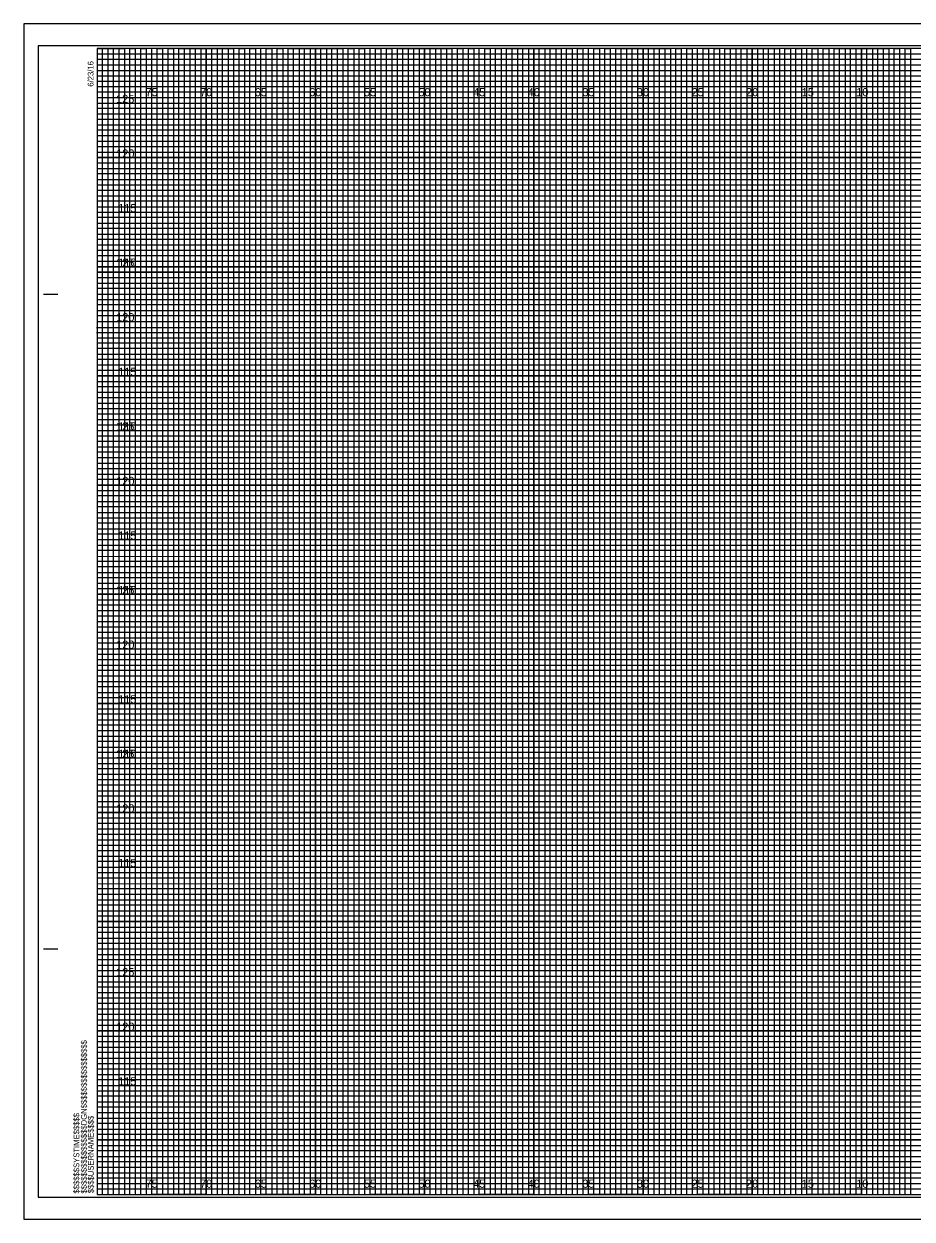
# Model space of a CAD drawing. Extents: x -7 to 182, y -2 to 1647.
# Drawn here: x -6.7 to 74.6, y 1427.8 to 1537.2 of the extents above; entities that cross this region are included whole.
import ezdxf

# ---------------------------------------------------------------- set-up
doc = ezdxf.new("R2010")
doc.units = 0
for name, color, linetype in [('Exist Cross Section Cell', 7, 'Continuous'), ('Exist XS Ground Line', 7, 'Continuous'), ('Prop CMT Pvmt Course 3', 7, 'Continuous'), ('Prop CMT Pvmt Wedge Surface 1', 7, 'Continuous'), ('Prop CMT Pvmt Wedge Surface 2', 7, 'Continuous'), ('Prop CMT Pvmt Wedge Surface 3', 7, 'Continuous'), ('Prop CMT Shld Paved Course 1', 7, 'Continuous'), ('Prop CMT Shld Paved Course 2', 7, 'Continuous'), ('Prop CMT Shld Paved Course 3', 7, 'Continuous'), ('Prop CMT Slope Grass', 7, 'Continuous'), ('Prop CMT Subgrade Earthwork', 7, 'Continuous')]:
    doc.layers.add(name, color=color, linetype=linetype)

msp = doc.modelspace()

# ---------------------------------------------------------------- linework, layer by layer
at = {"layer": 'Exist XS Ground Line'}
for p, q in [((5, 1535), (0, 1535)), ((5, 1430), (5, 1535)), ((15, 1535), (10, 1535)), ((10, 1535), (10, 1430)), ((15, 1430), (15, 1535)), ((25, 1535), (20, 1535)), ((20, 1535), (20, 1430)), ((25, 1430), (25, 1535)), ((35, 1535), (30, 1535)), ((30, 1535), (30, 1430)), ((35, 1430), (35, 1535)), ((45, 1535), (40, 1535)), ((40, 1535), (40, 1430)), ((45, 1430), (45, 1535)), ((55, 1535), (50, 1535)), ((50, 1535), (50, 1430)), ((55, 1430), (55, 1535)), ((65, 1535), (60, 1535)), ((60, 1535), (60, 1430)), ((65, 1430), (65, 1535)), ((75, 1535), (70, 1535)), ((70, 1535), (70, 1430)), ((10, 1430), (5, 1430)), ((20, 1430), (15, 1430)), ((30, 1430), (25, 1430)), ((40, 1430), (35, 1430)), ((50, 1430), (45, 1430)), ((60, 1430), (55, 1430)), ((70, 1430), (65, 1430))]:
    msp.add_line(p, q, dxfattribs=at)
for points in [[(0, 1530), (160, 1530), (160, 1525), (0, 1525)], [(0, 1520), (160, 1520), (160, 1515), (0, 1515)], [(0, 1510), (160, 1510), (160, 1505), (0, 1505)], [(0, 1500), (160, 1500), (160, 1495), (0, 1495)], [(0, 1490), (160, 1490), (160, 1485), (0, 1485)], [(0, 1480), (160, 1480), (160, 1475), (0, 1475)], [(0, 1470), (160, 1470), (160, 1465), (0, 1465)], [(0, 1460), (160, 1460), (160, 1455), (0, 1455)], [(0, 1450), (160, 1450), (160, 1445), (0, 1445)], [(0, 1440), (160, 1440), (160, 1435), (0, 1435)]]:
    msp.add_lwpolyline(points, dxfattribs=at)
at = {"layer": 'Prop CMT Pvmt Course 3'}
msp.add_lwpolyline([(-6.7, 1427.75), (161.65, 1427.75), (161.65, 1537.25), (-6.7, 1537.25)], close=True, dxfattribs=at)
at = {"layer": 'Prop CMT Pvmt Wedge Surface 1'}
for p, q in [((0, 1534.5), (130, 1534.5)), ((130, 1533.99), (0, 1533.99)), ((0, 1533.99), (0, 1533.5)), ((0, 1533.5), (130, 1533.5)), ((130, 1532.94), (0, 1532.94)), ((0, 1532.94), (0, 1532)), ((0, 1532), (160, 1532))]:
    msp.add_line(p, q, dxfattribs=at)
for points in [[(0, 1531.5), (135, 1531.5), (160, 1531.5), (160, 1531), (0, 1531)], [(0, 1530.5), (160, 1530.5), (160, 1529.5), (0, 1529.5)], [(0, 1529), (160, 1529), (160, 1528.5), (0, 1528.49)], [(0, 1528), (160, 1528), (160, 1527), (0, 1527)], [(0, 1526.5), (160, 1526.5), (160, 1526), (0, 1526)], [(0, 1525.5), (160, 1525.5), (160, 1524.5), (0, 1524.5)], [(0, 1524), (160, 1524), (160, 1523.5), (0, 1523.5)], [(0, 1523), (160, 1523), (160, 1522), (0, 1522)], [(0, 1521.5), (160, 1521.5), (160, 1521), (0, 1521)], [(0, 1520.5), (160, 1520.5), (160, 1519.5), (0, 1519.5)], [(0, 1519), (160, 1519), (160, 1518.5), (0, 1518.5)], [(0, 1518), (160, 1518), (160, 1516.98), (160, 1516.5), (160, 1516), (0, 1516)], [(0, 1517), (160, 1517), (160, 1516.5), (0, 1516.5)], [(0, 1515.5), (160, 1515.5), (160, 1514.5), (0, 1514.52)], [(0, 1514.52), (160, 1514.5), (160, 1514), (0, 1514)], [(0, 1513.5), (160, 1513.5), (160, 1513), (0, 1513)], [(0, 1512), (160, 1512), (160, 1511.5), (0, 1511.5)], [(0, 1511), (160, 1511), (160, 1510.5), (0, 1510.5)], [(-0.04, 1509.44), (160, 1509.44), (160, 1508.94), (-0.04, 1508.94)], [(0, 1508.5), (160, 1508.5), (160, 1508), (0, 1508)], [(0, 1507), (160, 1507), (160, 1506.5), (0, 1506.5)], [(0, 1506), (160, 1506), (160, 1505.5), (0, 1505.5)], [(0, 1504.5), (160, 1504.5), (160, 1504), (0, 1504)], [(0, 1503.5), (160, 1503.5), (160, 1503), (0, 1503)], [(0, 1502), (160, 1502), (160, 1501.5), (0, 1501.5)], [(0, 1501), (160, 1501), (160, 1500.5), (0, 1500.5)], [(0, 1499.5), (160, 1499.5), (160, 1498.99), (0, 1499)], [(0, 1498.5), (160, 1498.5), (160, 1498), (0, 1498)], [(0, 1497), (160, 1497), (160, 1496.5), (0, 1496.5)], [(0, 1496), (160, 1496), (160, 1495.5), (0, 1495.5)], [(0, 1494.5), (160, 1494.5), (160, 1494), (0, 1494)], [(0, 1493.5), (160, 1493.5), (160, 1493), (0, 1493)], [(0, 1492), (160, 1492), (160, 1491.5), (0, 1491.5)], [(0, 1491), (160, 1491), (160, 1490.5), (0, 1490.5)], [(0, 1489.5), (160, 1489.5), (160, 1489), (0, 1489)], [(0, 1488.5), (160.03, 1488.45), (160, 1488), (0, 1488)], [(0, 1487), (160, 1487), (160, 1486.5), (0, 1486.5)], [(0, 1486), (160, 1486), (160, 1485.5), (0, 1485.5)], [(0, 1484.5), (160, 1484.5), (160, 1484), (0, 1484)], [(0, 1483.5), (160, 1483.5), (160, 1483), (0, 1483)], [(0, 1482), (160, 1482), (160, 1481.5), (0, 1481.5)], [(0, 1481), (160, 1481), (160, 1480.5), (0, 1480.5)], [(0, 1479.5), (160, 1479.5), (160, 1479), (0, 1479)], [(0, 1478.5), (160, 1478.5), (160, 1478), (0, 1478)], [(0, 1477), (160, 1477), (160, 1476.5), (0, 1476.5)], [(0, 1476), (160, 1476), (160, 1475.5), (0, 1475.5)], [(0, 1474.5), (160, 1474.5), (160, 1474), (0, 1474)], [(0, 1473.5), (160, 1473.5), (160, 1473), (0, 1473)], [(0, 1472), (160, 1472), (160, 1471.5), (0, 1471.5)], [(0, 1471), (160, 1471), (160, 1470.5), (0, 1470.5)], [(0, 1469.5), (160, 1469.5), (160, 1468.99), (0, 1469)], [(0, 1468.5), (160, 1468.5), (160, 1468), (0, 1468)], [(0, 1467), (160, 1467), (160, 1466.5), (0, 1466.5)], [(0, 1466), (160, 1466), (160, 1465.5), (0, 1465.5)], [(0, 1464.5), (160, 1464.5), (160, 1464), (0, 1464)], [(0, 1463.5), (160, 1463.5), (160, 1463), (0, 1463)], [(0, 1462), (160, 1462), (160, 1461.5), (0, 1461.5)], [(0, 1461), (160, 1461), (160, 1460.5), (0, 1460.5)], [(0, 1459.5), (160, 1459.5), (160, 1459), (0, 1459)], [(0, 1458.5), (160.03, 1458.45), (160, 1458), (0, 1458)], [(0, 1457), (160, 1457), (160, 1456.5), (0, 1456.5)], [(0, 1456), (160, 1456), (160, 1455.5), (0, 1455.5)], [(0, 1454.5), (160, 1454.5), (160, 1454), (0, 1454)], [(0, 1453.5), (160, 1453.5), (160, 1453), (0, 1453)], [(0, 1452), (160, 1452), (160, 1451.5), (0, 1451.5)], [(0, 1451), (160, 1451), (160, 1450.5), (0, 1450.5)], [(0, 1449.5), (160, 1449.5), (160, 1449), (0, 1449)], [(0, 1448.5), (160, 1448.5), (160, 1448), (0, 1448)], [(0, 1447), (160, 1447), (160, 1446.5), (0, 1446.5)], [(0, 1446), (160, 1446), (160, 1445.5), (0, 1445.5)], [(0, 1444.5), (160, 1444.5), (160, 1444), (0, 1444)], [(0, 1443.5), (160, 1443.5), (160, 1443), (0, 1443)], [(0, 1442), (160, 1442), (160, 1441.5), (0, 1441.5)], [(0, 1441), (160, 1441), (160, 1440.5), (0, 1440.5)], [(0, 1439.5), (160, 1439.5), (160, 1439), (0, 1439)], [(0, 1438.5), (160, 1438.5), (160, 1438), (0, 1438)], [(0, 1437), (160, 1437), (160, 1436.5), (0, 1436.5)], [(0, 1436), (160, 1436), (160, 1435.5), (0, 1435.5)], [(0, 1434.5), (160, 1434.5), (160, 1434), (0, 1434)], [(0, 1433.5), (160, 1433.5), (160, 1433), (0, 1433)], [(0, 1432), (160, 1432), (160, 1431.5), (0, 1431.5)], [(0, 1431), (160, 1431), (160, 1430.5), (0, 1430.5)]]:
    msp.add_lwpolyline(points, dxfattribs=at)
at = {"layer": 'Prop CMT Pvmt Wedge Surface 2'}
for p, q in [((-4.9, 1512.5), (-3.65, 1512.5)), ((-4.85, 1512.5), (-3.6, 1512.5)), ((-4.9, 1452.5), (-3.65, 1452.5)), ((-4.85, 1452.5), (-3.6, 1452.5)), ((0, 1430), (0, 1430)), ((0, 1430), (0, 1430)), ((0, 1430), (0, 1430)), ((0, 1430), (0, 1430)), ((0, 1430), (0, 1430)), ((0, 1430), (0, 1430)), ((0, 1430), (0, 1430))]:
    msp.add_line(p, q, dxfattribs=at)
msp.add_lwpolyline([(160, 1535), (0, 1535), (0, 1430), (160, 1430)], close=True, dxfattribs=at)
at = {"layer": 'Prop CMT Pvmt Wedge Surface 3'}
for points in [[(0, 1430), (0.5, 1430), (0.5, 1535), (1, 1535), (1, 1430)], [(1, 1430), (1.5, 1430), (1.5, 1535), (2, 1535), (2, 1430)], [(2.5, 1430), (3, 1430), (3, 1535), (3.5, 1535), (3.5, 1430)], [(3.5, 1430), (4, 1430), (4, 1535), (4.5, 1535), (4.5, 1430)], [(5, 1430), (5.5, 1430), (5.5, 1535), (6, 1535), (6, 1430)], [(6, 1430), (6.5, 1430), (6.5, 1535), (7, 1535), (7, 1430)], [(7.5, 1430), (8, 1430), (8, 1535), (8.5, 1535), (8.5, 1430)], [(8.5, 1430), (9, 1430), (9, 1535), (9.5, 1535), (9.5, 1430)], [(10, 1430), (10.5, 1430), (10.5, 1535), (11, 1535), (11, 1430)], [(11, 1430), (11.5, 1430), (11.5, 1535), (12, 1535), (12, 1430)], [(12.5, 1430), (13, 1430), (13, 1535), (13.5, 1535), (13.5, 1430)], [(13.5, 1430), (14, 1430), (14, 1535), (14.5, 1535), (14.5, 1430)], [(15, 1430), (15.5, 1430), (15.5, 1535), (16, 1535), (16, 1430)], [(16, 1430), (16.5, 1430), (16.5, 1535), (17, 1535), (17, 1430)], [(17.5, 1430), (18, 1430), (18, 1535), (18.5, 1535), (18.5, 1430)], [(18.5, 1430), (19, 1430), (19, 1535), (19.5, 1535), (19.5, 1430)], [(20, 1430), (20.5, 1430), (20.5, 1535), (21, 1535), (21, 1430)], [(21, 1430), (21.5, 1430), (21.5, 1535), (22, 1535), (22, 1430)], [(22.5, 1430), (23, 1430), (23, 1535), (23.5, 1535), (23.5, 1430)], [(23.5, 1430), (24, 1430), (24, 1535), (24.5, 1535), (24.5, 1430)], [(25, 1430), (25.5, 1430), (25.5, 1535), (26, 1535), (26, 1430)], [(26, 1430), (26.5, 1430), (26.5, 1535), (27, 1535), (27, 1430)], [(27.5, 1430), (28, 1430), (28, 1535), (28.5, 1535), (28.5, 1430)], [(28.5, 1430), (29, 1430), (29, 1535), (29.5, 1535), (29.5, 1430)], [(30, 1430), (30.5, 1430), (30.5, 1535), (31, 1535), (31, 1430)], [(31, 1430), (31.5, 1430), (31.5, 1535), (32, 1535), (32, 1430)], [(32.5, 1430), (33, 1430), (33, 1535), (33.5, 1535), (33.5, 1430)], [(33.5, 1430), (34, 1430), (34, 1535), (34.5, 1535), (34.5, 1430)], [(35, 1430), (35.5, 1430), (35.5, 1535), (36, 1535), (36, 1430)], [(36, 1430), (36.5, 1430), (36.5, 1535), (37, 1535), (37, 1430)], [(37.5, 1430), (38, 1430), (38, 1535), (38.5, 1535), (38.5, 1430)], [(38.5, 1430), (39, 1430), (39, 1535), (39.5, 1535), (39.5, 1430)], [(40, 1430), (40.5, 1430), (40.5, 1535), (41, 1535), (41, 1430)], [(41, 1430), (41.5, 1430), (41.5, 1535), (42, 1535), (42, 1430)], [(42.5, 1430), (43, 1430), (43, 1535), (43.5, 1535), (43.5, 1430)], [(43.5, 1430), (44, 1430), (44, 1535), (44.5, 1535), (44.5, 1430)], [(45, 1430), (45.5, 1430), (45.5, 1535), (46, 1535), (46, 1430)], [(46, 1430), (46.5, 1430), (46.5, 1535), (47, 1535), (47, 1430)], [(47.5, 1430), (48, 1430), (48, 1535), (48.5, 1535), (48.5, 1430)], [(48.5, 1430), (49, 1430), (49, 1535), (49.5, 1535), (49.5, 1430)], [(50, 1430), (50.5, 1430), (50.5, 1535), (51, 1535), (51, 1430)], [(51, 1430), (51.5, 1430), (51.5, 1535), (52, 1535), (52, 1430)], [(52.5, 1430), (53, 1430), (53, 1535), (53.5, 1535), (53.5, 1430)], [(53.5, 1430), (54, 1430), (54, 1535), (54.5, 1535), (54.5, 1430)], [(55, 1430), (55.5, 1430), (55.5, 1535), (56, 1535), (56, 1430)], [(56, 1430), (56.5, 1430), (56.5, 1535), (57, 1535), (57, 1430)], [(57.5, 1430), (58, 1430), (58, 1535), (58.5, 1535), (58.5, 1430)], [(58.5, 1430), (59, 1430), (59, 1535), (59.5, 1535), (59.5, 1430)], [(60, 1430), (60.5, 1430), (60.5, 1535), (61, 1535), (61, 1430)], [(61, 1430), (61.5, 1430), (61.5, 1535), (62, 1535), (62, 1430)], [(62.5, 1430), (63, 1430), (63, 1535), (63.5, 1535), (63.5, 1430)], [(63.5, 1430), (64, 1430), (64, 1535), (64.5, 1535), (64.5, 1430)], [(65, 1430), (65.5, 1430), (65.5, 1535), (66, 1535), (66, 1430)], [(66, 1430), (66.5, 1430), (66.5, 1535), (67, 1535), (67, 1430)], [(67.5, 1430), (68, 1430), (68, 1535), (68.5, 1535), (68.5, 1430)], [(68.5, 1430), (69, 1430), (69, 1535), (69.5, 1535), (69.5, 1430)], [(70, 1430), (70.5, 1430), (70.5, 1535), (71, 1535), (71, 1430)], [(71, 1430), (71.5, 1430), (71.5, 1535), (72, 1535), (72, 1430)], [(72.5, 1430), (73, 1430), (73, 1535), (73.5, 1535), (73.5, 1430)], [(73.5, 1430), (74, 1430), (74, 1535), (74.5, 1535), (74.5, 1430)]]:
    msp.add_lwpolyline(points, dxfattribs=at)
at = {"layer": 'Prop CMT Shld Paved Course 1'}
for p, q in [((5, 1430), (5, 1535)), ((10, 1430), (10, 1535)), ((15, 1430), (15, 1535)), ((20, 1430), (20, 1535)), ((25, 1430), (25, 1535)), ((30, 1430), (30, 1535)), ((35, 1430), (35, 1535)), ((40, 1430), (40, 1535)), ((45, 1430), (45, 1535)), ((50, 1430), (50, 1535)), ((55, 1430), (55, 1535)), ((60, 1430), (60, 1535)), ((65, 1430), (65, 1535)), ((70, 1430), (70, 1535)), ((0, 1530), (160, 1530)), ((0, 1525), (160, 1525)), ((0, 1520), (160, 1520)), ((0, 1515), (160, 1515)), ((0, 1510), (160, 1510)), ((0, 1505), (160, 1505)), ((0, 1500), (160, 1500)), ((0, 1495), (160, 1495)), ((0, 1490), (160, 1490)), ((0, 1485), (160, 1485)), ((0, 1480), (160, 1480)), ((0, 1475), (160, 1475)), ((0, 1470), (160, 1470)), ((0, 1465), (160, 1465)), ((0, 1460), (160, 1460)), ((0, 1455), (160, 1455)), ((0, 1450), (160, 1450)), ((0, 1445), (160, 1445)), ((0, 1440), (160, 1440)), ((0, 1435), (160, 1435))]:
    msp.add_line(p, q, dxfattribs=at)
at = {"layer": 'Prop CMT Shld Paved Course 2'}
for p, q in [((161.65, 1537.25), (-6.7, 1537.25)), ((-6.7, 1537.25), (-6.7, 1427.75)), ((-6.7, 1427.75), (161.65, 1427.75))]:
    msp.add_line(p, q, dxfattribs=at)
at = {"layer": 'Prop CMT Slope Grass'}
msp.add_lwpolyline([(-5.4, 1429.75), (161.2, 1429.75), (161.2, 1535.25), (-5.4, 1535.25)], close=True, dxfattribs=at)
at = {"layer": 'Prop CMT Subgrade Earthwork'}
for points in [[(0, 1535), (2.5, 1535), (2.5, 1430), (7.5, 1430), (7.5, 1535), (12.5, 1535), (12.5, 1430), (17.5, 1430), (17.5, 1535), (22.5, 1535), (22.5, 1430), (27.5, 1430), (27.5, 1535), (32.5, 1535), (32.5, 1430), (37.5, 1430), (37.5, 1535), (42.5, 1535), (42.5, 1430), (47.5, 1430), (47.5, 1535), (52.5, 1535), (52.5, 1430), (57.5, 1430), (57.5, 1535), (62.5, 1535), (62.5, 1430), (67.5, 1430), (67.5, 1535), (72.5, 1535), (72.5, 1430), (77.5, 1430)], [(0, 1532.5), (137.5, 1532.5)], [(0, 1522.5), (160, 1522.5), (160, 1527.5), (0, 1527.5)], [(0, 1512.5), (160, 1512.5), (160, 1517.5), (0, 1517.5)], [(0, 1502.5), (160, 1502.5), (160, 1507.5), (0, 1507.5)], [(0, 1492.5), (160, 1492.5), (160, 1497.5), (0, 1497.5)], [(0, 1482.5), (160, 1482.5), (160, 1487.5), (0, 1487.5)], [(0, 1472.5), (160, 1472.5), (160, 1477.5), (0, 1477.5)], [(0, 1462.5), (160, 1462.5), (160, 1467.5), (0, 1467.5)], [(0, 1452.5), (160, 1452.5), (160, 1457.5), (0, 1457.5)], [(0, 1442.5), (160, 1442.5), (160, 1447.5), (0, 1447.5)], [(0, 1432.5), (160, 1432.5), (160, 1437.5), (0, 1437.5)]]:
    msp.add_lwpolyline(points, dxfattribs=at)

# ---------------------------------------------------------------- texts
at = {"layer": 'Exist Cross Section Cell'}
for s, p in [('75', (4.44, 1530.62)), ('70', (9.43, 1530.62)), ('65', (14.44, 1530.62)), ('60', (19.43, 1530.62)), ('55', (24.44, 1530.62)), ('50', (29.43, 1530.62)), ('45', (34.44, 1530.62)), ('40', (39.43, 1530.62)), ('35', (44.44, 1530.62)), ('30', (49.43, 1530.62)), ('25', (54.44, 1530.62)), ('20', (59.43, 1530.62)), ('15', (64.53, 1530.62)), ('10', (69.52, 1530.62)), ('75', (4.44, 1430.62)), ('70', (9.43, 1430.62)), ('65', (14.44, 1430.62)), ('60', (19.43, 1430.62)), ('55', (24.44, 1430.62)), ('50', (29.43, 1430.62)), ('45', (34.44, 1430.62)), ('40', (39.43, 1430.62)), ('35', (44.44, 1430.62)), ('30', (49.43, 1430.62)), ('25', (54.44, 1430.62)), ('20', (59.43, 1430.62)), ('15', (64.53, 1430.62)), ('10', (69.52, 1430.62))]:
    msp.add_text(s, height=0.75, dxfattribs=at).set_placement(p)
at = {"layer": 'Prop CMT Pvmt Wedge Surface 2'}
for s, p in [('6/23/16', (-0.33, 1531.5)), ('$$$$$$$$$$$$$$$$DGN$$$$$$$$$$$$$$$$', (-0.94, 1430.09)), ('$$$$$$SYSTIME$$$$$', (-1.63, 1430.09)), ('$$$$USERNAME$$$$', (-0.31, 1430.12))]:
    msp.add_text(s, height=0.525, rotation=90, dxfattribs=at).set_placement(p)
at = {"layer": 'Prop CMT Shld Paved Course 3'}
for s, p in [('125', (1.74, 1530)), ('120', (1.75, 1525)), ('115', (1.93, 1520)), ('125', (1.74, 1515)), ('110', (1.94, 1515)), ('120', (1.75, 1510)), ('115', (1.93, 1505)), ('125', (1.74, 1500)), ('110', (1.94, 1500)), ('120', (1.75, 1495)), ('115', (1.93, 1490)), ('125', (1.74, 1485)), ('110', (1.94, 1485)), ('120', (1.75, 1480)), ('115', (1.93, 1475)), ('125', (1.74, 1470)), ('110', (1.94, 1470)), ('120', (1.75, 1465)), ('115', (1.93, 1460)), ('125', (1.74, 1450)), ('120', (1.75, 1445)), ('115', (1.93, 1440))]:
    msp.add_text(s, height=0.75, dxfattribs=at).set_placement(p)

doc.saveas('drawing.dxf')
